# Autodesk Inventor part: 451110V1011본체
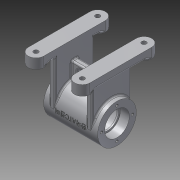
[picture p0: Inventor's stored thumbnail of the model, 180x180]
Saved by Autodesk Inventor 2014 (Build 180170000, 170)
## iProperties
Created: 2015-11
Part Number: 451110V1011본체
Material: Aluminum 6061
Document SubType Name: Modeling
Designer: user
Density: 2.71 g/cm^3
Appearance: Aluminum - Flat
Author: user
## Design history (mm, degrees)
sketch "Sketch1"
  geometry: L1 (0, 0)-(20, 0); L2 (20, 0)-(20, 80); L3 (20, 80)-(0, 80); L4 (0, 80)-(0, 0); L5 (60, 80)-(80, 80); L6 (80, 80)-(80, 0); L7 (80, 0)-(60, 0); L8 (60, 0)-(60, 80)
  constraints: 16 end point, 4 parallel, 2 equal length, 2 horizontal, 2 perpendicular, 1 collinear
  dimensions: "d0" = 80 distance of L3.end L1.start; "d1" = 20 distance of L2.end L3.end; "d2" = 80 distance between parallel lines of L6 L4
extrude "Extrusion1" new body sketch "Sketch1" distance "d3" = 10; taper "d4" = 0 deg
sketch "Sketch2"
  geometry: L1 (20, 0)-(20, 80) reference; L2 (80, 0)-(80, 80) reference; C1 r 10 at (10, 0); C2 r 10 at (70, 0); 1 further point
  constraints: 2 centre point
  dimensions: "d5" = 20 diameter of C1; "d6" = 10 distance from line of L1 C1.centre; "d7" = 20 diameter of C2; "d8" = 10 distance from line of L2 C2.centre
extrude "Extrusion2" join sketch "Sketch2" distance "d9" = 13; taper "d10" = 0 deg
workplane "Work Plane1"
mirror "Mirror1"
workplane "Work Plane2"
sketch "Sketch3"
  geometry: L1 (0, 10)-(80, 10) reference; L2 (90, -3)-(90, 10) reference; C1 r 25 at (40, -58); 1 further point
  constraints: 1 centre point
  dimensions: "d13" = 50 diameter of C1; "d14" = 68 distance from line of L1 C1.centre; "d15" = 50 distance from line of L2 C1.centre
extrude "Extrusion3" join sketch "Sketch3" distance "d16" = 70; taper "d17" = 0 deg
sketch "Sketch4"
  geometry: L1 (-60, 80)-(-60, 0) reference; L2 (-80, 0)-(-80, 80) reference; L3 (0, 80)-(0, 0) reference; L4 (-20, 0)-(-20, 80) reference; L5 (-60, 15)-(-68, 15); L6 (-68, 15)-(-68, 65); L7 (-68, 65)-(-60, 65); L8 (-20, 65)-(-12, 65); L9 (-12, 65)-(-12, 15); L10 (-12, 15)-(-20, 15); L11 (-20, 65)-(-20, 15); L12 (-60, 65)-(-60, 15); A1 r 10 centre (-70, 0) between (-80, 0) and (-60, 0) reference; A2 r 10 centre (-70, 80) between (-60, 80) and (-80, 80) reference; A3 r 10 centre (-10, 0) between (-20, 0) and (0, 0) reference; A4 r 10 centre (-10, 80) between (0, 80) and (-20, 80) reference; 1 further point
  constraints: 16 end point, 5 perpendicular, 4 point on line, 3 collinear
  dimensions: "d18" = 8 distance between parallel lines of L12 L6; "d19" = 8 distance between parallel lines of L9 L11; "d20" = 50 distance of L5.end L6.end; "d21" = 50 distance of L8.end L9.end; "d22" = 15 distance from line of A1.centre L5; "d23" = 15 distance from line of A3.centre L10
extrude "Extrusion4" join sketch "Sketch4" stored distance "d24" = 70; taper "d25" = 0 deg
workplane "Work Plane3"
sketch "Sketch5"
  geometry: L1 (75, 15)-(75, 65) reference; L2 (12, 65)-(20, 65) reference; L3 (20, 65)-(20, 15) reference; L4 (12, 15)-(20, 15) reference; L5 (12, 15)-(12, 65) reference; L6 (5, 65)-(5, 15) reference; L7 (60, 15)-(68, 15) reference; L8 (60, 15)-(60, 65) reference; L9 (60, 65)-(68, 65) reference; L10 (68, 65)-(68, 15) reference; C1 r 5 at (40, 40); 1 further point
  constraints: 1 centre point
  dimensions: "d27" = 10 diameter of C1; "d36" = 25 distance from line of C1.centre L7; "d76" = 35 distance from line of C1.centre L1
extrude "Extrusion5" join sketch "Sketch5" stored distance "d28" = 70; taper "d29" = 0 deg
workplane "Work Plane4"
sketch "Sketch6"
  geometry: L1 (60, 15)-(68, 15) reference; L2 (60, 15)-(60, 65) reference; L3 (60, 65)-(68, 65) reference; L4 (68, 65)-(68, 15) reference; L5 (5, 65)-(5, 15) reference; L6 (12, 65)-(20, 65) reference; L7 (20, 65)-(20, 15) reference; L8 (12, 15)-(20, 15) reference; L9 (12, 15)-(12, 65) reference; L10 (75, 15)-(75, 65) reference; L11 (20, 44)-(60, 44); L12 (60, 44)-(60, 36); L13 (60, 36)-(20, 36); L14 (20, 36)-(20, 44); 3 further points
  constraints: 8 end point, 2 collinear, 2 parallel, 1 horizontal, 1 midpoint, 1 perpendicular, 1 other
  dimensions: "d32" = 25 distance from line of L3 point (60, 40); "d33" = 8 distance of L13.end L11.start
extrude "Extrusion6" join sketch "Sketch6" stored distance "d34" = 70; taper "d35" = 0 deg
sketch "Sketch7"
  geometry: L1 (12, 10)-(28, 10); L2 (12, 6.5)-(28, 6.5); L3 (28, 13.5)-(12, 13.5); L4 (40, -23)-(60, -23) reference; L5 (-15, 70)-(-15, 20) reference; A1 r 3.5 centre (12, 10) between (12, 13.5) and (12, 6.5); A2 r 3.5 centre (28, 10) between (28, 6.5) and (28, 13.5); 2 further points
  constraints: 8 end point, 4 point on circle, 4 tangent, 2 centre point, 1 horizontal, 1 midpoint, 1 parallel
  dimensions: "d37" = 3.5 radius of A2; "d38" = 33 distance from line of L4 point (20, 10); "d40" = 23 dimension on A2 A1; "d41" = 35 distance from line of point (20, 10) L5
extrude "Extrusion7" cut sketch "Sketch7" stored distance "d42" = 70; taper "d43" = 0 deg
hole "Hole1" diameter "d46" = 28; stored, may be unused: countersink angle "d50" = 90 deg, drill point angle "d52" = 0 deg; dims "d47" = 6, "d48" = 32, "d49" = 12, "d51" = 14, "d53" = 10, "d54" = 10
workplane "Work Plane5"
mirror "Mirror2"
workplane "Work Plane6"
sketch "Sketch8"
  geometry: C1 r 21 at (0, 0); 1 further point
  constraints: 1 centre point
  dimensions: "d56" = 42 diameter of C1
extrude "Extrusion8" cut sketch "Sketch8" distance "d57" = 42; taper "d58" = 0 deg
sketch "Sketch9"
  geometry: 2 further points
hole "Hole2" sketch "Sketch9" at (-20, 0) diameter "d60" = 3.242; stored, may be unused: countersink angle "d64" = 90 deg, drill point angle "d66" = 118 deg; dims "d61" = 8, "d62" = 4, "d63" = 8, "d65" = 10
pattern_circular "Circular Pattern1" dims angle "d68" = 360 deg
workplane "Work Plane7"
mirror "Mirror3"
workplane "Work Plane9"
  workplane "Work Plane8"
sketch "Sketch10"
  geometry: L1 (-7, -83)-(63, -83) reference; L2 (63, -83)-(63, -33) reference; 3 further points
  constraints: 1 other
  dimensions: "d77" = 25 distance from line of point (28, -58) L1; "d78" = 35 distance from line of point (28, -58) L2
emboss "Emboss1" sketch "Sketch10" dims "d9" = 13, "d10" = 0, "d79" = 0.5, "d80" = 0
hole "Hole3" diameter "d83" = 6; stored, may be unused: countersink angle "d87" = 90 deg, drill point angle "d89" = 0 deg; dims "d84" = 6, "d85" = 4, "d86" = 8, "d88" = 10, "d90" = 10, "d91" = 10
workplane "Work Plane11"
sketch "Sketch11"
  geometry: L1 (-58, 25)-(-33.751, 39); L2 (-58, 25)-(-30, 25); C1 r 14 at (-58, 25) reference; 1 further point
  constraints: 4 end point, 1 equal length, 1 horizontal
  dimensions: "d92" = 28 distance of L1.start L1.end; "d93" = 30 deg angle of L2 L1
workplane "Work Plane12"
sketch "Sketch12"
  geometry: L1 (0, 0)-(28, 0) reference; L2 (28, 0)-(22.856, 0); L3 (22.856, 0)-(22.856, 6); L4 (22.856, 6)-(28, 6); L5 (28, 6)-(28, 0); 1 further point
  constraints: 8 end point, 2 parallel, 1 horizontal, 1 perpendicular
  dimensions: "d95" = 6 distance of L2.end L3.end
revolve "Revolution1" sketch "Sketch12" stored, may be unused: angle "d96" = 90 deg
hole "Hole4" diameter "d99" = 6; stored, may be unused: countersink angle "d103" = 90 deg, drill point angle "d105" = 0 deg; dims "d97" = 10, "d98" = 10, "d100" = 6, "d101" = 12, "d102" = 4, "d104" = 10
pattern_linear "Rectangular Pattern1" dims "d112" = 60
fillet "Fillet1" dims "d106" = 0.3
chamfer "Chamfer1" distance "d107" = 1; stored, may be unused: second distance "d108" = 2, angle "d109" = 45 deg
fillet "Fillet2" dims "d116" = 3.5
fillet "Fillet3" dims "d117" = 3
fillet "Fillet4" dims "d118" = 2
fillet "Fillet5" dims "d119" = 2
fillet "Fillet6" dims "d120" = 2
fillet "Fillet7" dims "d121" = 0.3
hole "Hole5" diameter "d124" = 4.917; stored, may be unused: countersink angle "d128" = 90 deg, drill point angle "d130" = 0 deg; dims "d122" = 10, "d123" = 10, "d125" = 13, "d126" = 12, "d127" = 4, "d129" = 13
body "Solid1"
node "Projected Loop1"
node "Projected Loop2"
node "Projected Loop3"
node "Projected Loop4"
other parameters: "d12" = 5, "d26" = -96, "d30" = -23, "d55" = -14, "d73" = 25.5, "d94" = 90 deg
